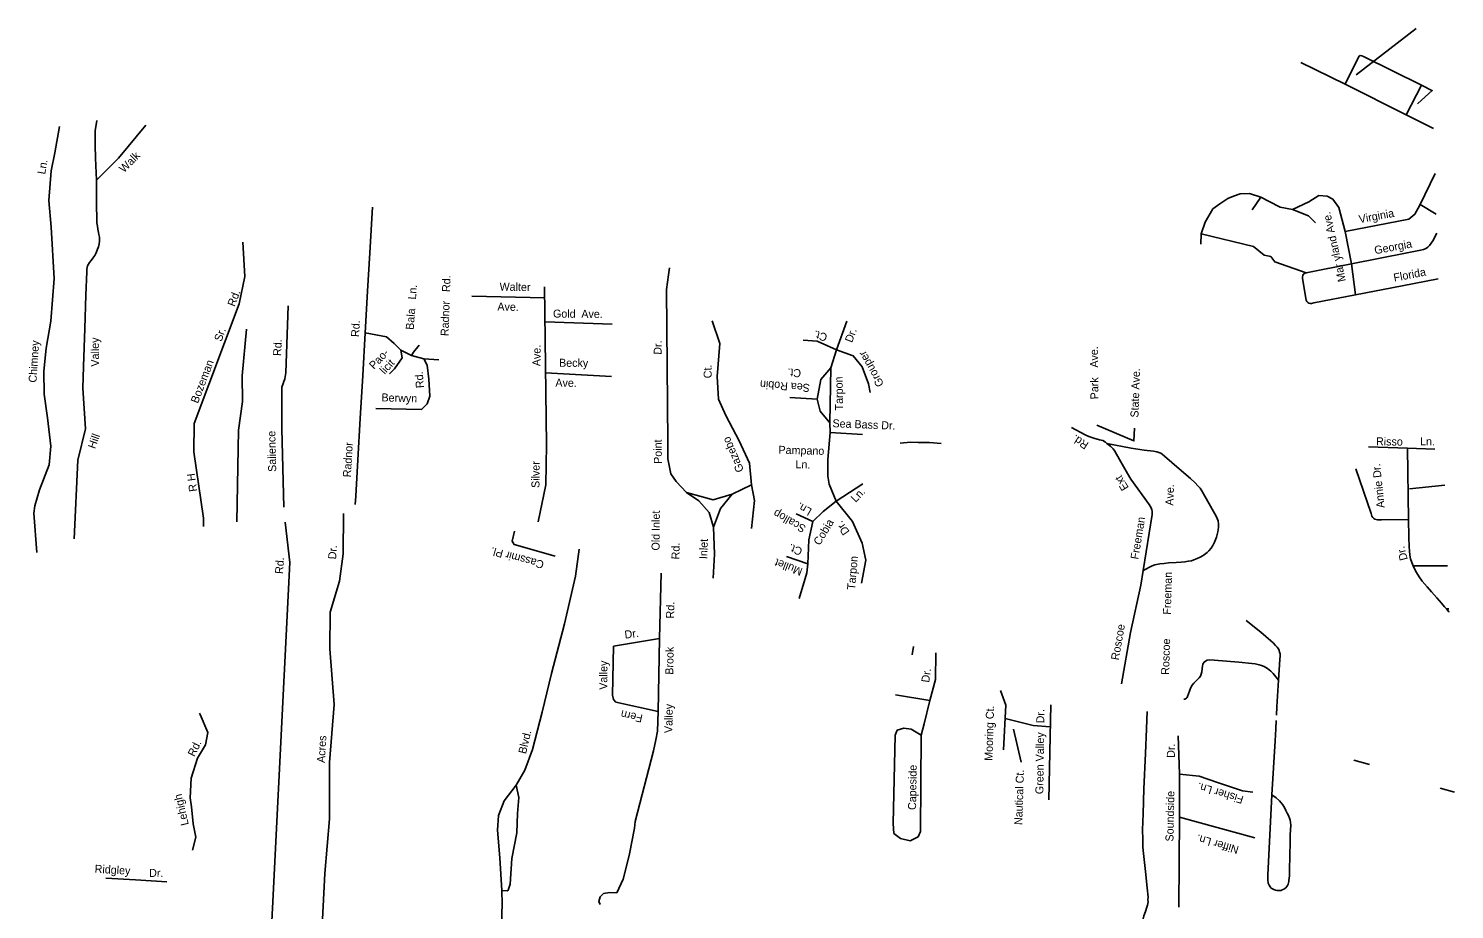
# Model space of a CAD drawing. Extents: x 2308163 to 2335412, y -96774 to 125428.
# Drawn here: x 2322147.6 to 2322238.9, y 82531.3 to 82587.7 of the extents above; entities that cross this region are included whole.
import ezdxf

# ---------------------------------------------------------------- set-up
doc = ezdxf.new("R2010")
doc.units = 0
doc.layers.add('Old_Level_10', color=7, linetype='Continuous')
doc.layers.add('Old_Level_35', color=7, linetype='Continuous')

msp = doc.modelspace()

# ---------------------------------------------------------------- linework, layer by layer
at = {"layer": 'Old_Level_10'}
for points in [[(2322236.457, 82587.723), (2322232.616, 82584.764)], [(2322237.499, 82583.786), (2322236.549, 82582.911)], [(2322218.414, 82562.132), (2322218.386, 82561.327), (2322216, 82562.337)], [(2322211.158, 82540.763), (2322210.667, 82542.876)]]:
    msp.add_lwpolyline(points, dxfattribs=at)
at = {"layer": 'Old_Level_35'}
for p, q in [((2322229.076, 82585.559), (2322231.904, 82584.161)), ((2322231.904, 82584.161), (2322235.826, 82582.192)), ((2322235.826, 82582.192), (2322236.808, 82584.088)), ((2322237.501, 82583.743), (2322236.808, 82584.088)), ((2322237.577, 82581.313), (2322235.826, 82582.192)), ((2322232.578, 82570.684), (2322232.312, 82572.661)), ((2322158.791, 82556.379), (2322158.186, 82560.62)), ((2322235.968, 82556.299), (2322235.901, 82560.854)), ((2322168.517, 82557.251), (2322168.547, 82557.791)), ((2322158.794, 82555.846), (2322158.791, 82556.379)), ((2322204.186, 82547.638), (2322204.259, 82548.168)), ((2322227.54, 82544.297), (2322227.635, 82546.009)), ((2322219.21, 82543.472), (2322219.23, 82544.005)), ((2322227.51, 82543.769), (2322227.54, 82544.297)), ((2322219.188, 82542.899), (2322219.21, 82543.472)), ((2322227.486, 82543.417), (2322227.464, 82542.889)), ((2322227.464, 82542.889), (2322227.432, 82542.121)), ((2322227.432, 82542.121), (2322227.226, 82538.671)), ((2322233.478, 82540.616), (2322232.468, 82540.875)), ((2322238.915, 82538.845), (2322238.006, 82539.101))]:
    msp.add_line(p, q, dxfattribs=at)
for points in [[(2322236.808, 82584.088), (2322233.086, 82585.929), (2322232.976, 82585.985), (2322232.884, 82586), (2322232.807, 82585.954), (2322232.774, 82585.89), (2322231.904, 82584.161)], [(2322149.281, 82579.757), (2322149.577, 82581.451)], [(2322151.947, 82578.012), (2322151.889, 82579.421), (2322151.862, 82580.249), (2322151.852, 82580.592), (2322151.867, 82581.171), (2322151.961, 82581.825)], [(2322155.112, 82581.546), (2322153.357, 82579.416), (2322151.947, 82578.012)], [(2322148.115, 82554.183), (2322147.93, 82556.697), (2322147.986, 82557.171), (2322148.299, 82558.191), (2322148.91, 82559.795), (2322149.03, 82560.979), (2322148.815, 82562.81), (2322148.59, 82564.324), (2322148.561, 82565.791), (2322148.731, 82567.252), (2322149.028, 82568.985), (2322149.242, 82571.713), (2322149.038, 82575.009), (2322148.899, 82576.718), (2322149.043, 82578.615), (2322149.281, 82579.757)], [(2322151.079, 82564.694), (2322151.112, 82566.089), (2322151.187, 82568.526), (2322151.254, 82570.663), (2322151.323, 82572.147), (2322151.325, 82572.321), (2322151.337, 82572.426), (2322151.362, 82572.539), (2322151.428, 82572.645), (2322151.497, 82572.737), (2322151.604, 82572.876), (2322151.718, 82573.03), (2322151.828, 82573.195), (2322151.917, 82573.364), (2322152.013, 82573.601), (2322152.063, 82573.757), (2322152.106, 82573.937), (2322152.128, 82574.101), (2322152.127, 82574.232), (2322152.127, 82574.365), (2322152.103, 82574.529), (2322152.079, 82574.662), (2322152.029, 82574.872), (2322152, 82575.061), (2322151.976, 82575.276), (2322151.946, 82576.667), (2322151.947, 82578.012)], [(2322236.697, 82576.415), (2322237.668, 82578.445)], [(2322232.312, 82572.661), (2322231.914, 82574.724), (2322231.503, 82576.263), (2322231.123, 82576.806), (2322230.764, 82576.985), (2322230.235, 82577.036), (2322229.591, 82576.627), (2322228.545, 82576.133), (2322227.755, 82576.293), (2322227.037, 82576.649), (2322226.516, 82576.932), (2322225.794, 82577.156), (2322225.196, 82577.143), (2322224.76, 82576.993), (2322224.39, 82576.84), (2322223.88, 82576.493), (2322223.438, 82576.176), (2322222.944, 82575.331), (2322222.686, 82574.578), (2322222.663, 82573.916)], [(2322226.516, 82576.932), (2322225.957, 82576.123)], [(2322168.547, 82557.791), (2322168.681, 82560.112), (2322168.836, 82562.767), (2322168.999, 82565.515), (2322169.158, 82568.244), (2322169.3, 82570.915), (2322169.455, 82573.365), (2322169.617, 82576.289)], [(2322228.545, 82576.133), (2322229.56, 82575.733), (2322230.009, 82575.287)], [(2322231.914, 82574.724), (2322236.002, 82575.511), (2322236.378, 82575.83), (2322236.697, 82576.415)], [(2322237.75, 82575.835), (2322236.716, 82576.455)], [(2322222.686, 82574.578), (2322226.042, 82573.766), (2322226.719, 82573.212), (2322227.148, 82573.131), (2322227.402, 82572.791), (2322229.427, 82572.078)], [(2322232.312, 82572.661), (2322235.878, 82573.373), (2322236.633, 82573.51), (2322236.838, 82573.552), (2322236.932, 82573.581), (2322237.042, 82573.627), (2322237.114, 82573.669), (2322237.201, 82573.731), (2322237.305, 82573.829), (2322237.425, 82573.975), (2322237.521, 82574.129), (2322237.788, 82574.621)], [(2322158.186, 82560.62), (2322158.201, 82562.431), (2322161.089, 82570.102), (2322161.435, 82571.854), (2322161.32, 82574.051)], [(2322191.436, 82552.543), (2322191.534, 82554.074), (2322191.458, 82555.792), (2322191.175, 82556.749), (2322190.523, 82557.494), (2322189.728, 82558.018), (2322189.074, 82558.717), (2322188.731, 82559.226), (2322188.538, 82560.18), (2322188.528, 82561.218), (2322188.46, 82571.015), (2322188.583, 82571.958), (2322188.643, 82572.408)], [(2322232.578, 82570.684), (2322229.908, 82570.156), (2322229.75, 82570.127), (2322229.68, 82570.127), (2322229.596, 82570.147), (2322229.532, 82570.18), (2322229.457, 82570.243), (2322229.408, 82570.323), (2322229.181, 82571.72), (2322229.183, 82571.828), (2322229.2, 82571.908), (2322229.233, 82571.985), (2322229.264, 82572.021), (2322229.345, 82572.062), (2322229.427, 82572.078), (2322232.312, 82572.661)], [(2322237.88, 82571.696), (2322235.563, 82571.253), (2322232.578, 82570.684)], [(2322175.988, 82570.587), (2322180.651, 82570.474)], [(2322180.232, 82556.134), (2322180.721, 82558.509), (2322180.764, 82561.08), (2322180.642, 82571.179)], [(2322163.933, 82557.08), (2322163.813, 82562.093), (2322163.814, 82564.756), (2322164.013, 82565.291), (2322164.071, 82565.673), (2322164.22, 82569.978)], [(2322180.669, 82568.937), (2322184.96, 82568.789)], [(2322193.9, 82558.506), (2322193.768, 82559.909), (2322193.094, 82561.332), (2322192.246, 82562.941), (2322191.786, 82563.995), (2322191.7, 82565.442), (2322191.863, 82567.558), (2322191.372, 82569.019)], [(2322199.32, 82557.461), (2322198.861, 82558.56), (2322198.788, 82559.059), (2322198.78, 82560.143), (2322198.929, 82561.853), (2322198.906, 82562.485), (2322198.982, 82566.003), (2322199.338, 82567.164), (2322199.989, 82568.992)], [(2322160.926, 82556.15), (2322161.032, 82562.009), (2322161.299, 82563.85), (2322161.265, 82565.499), (2322161.548, 82568.468)], [(2322169.158, 82568.244), (2322170.524, 82567.978), (2322171.006, 82567.555), (2322171.443, 82567.134), (2322171.516, 82566.635), (2322171.04, 82565.929), (2322170.714, 82565.624)], [(2322199.338, 82567.164), (2322198.092, 82567.704), (2322197.192, 82567.78)], [(2322171.443, 82567.134), (2322172.109, 82566.795), (2322172.252, 82567.015), (2322172.619, 82567.46)], [(2322199.338, 82567.164), (2322200.409, 82566.766), (2322200.972, 82566.07), (2322201.385, 82564.972), (2322201.502, 82564.427)], [(2322172.915, 82566.586), (2322173.126, 82566.173), (2322173.231, 82565.267), (2322173.283, 82564.181), (2322173.131, 82563.69), (2322172.758, 82563.342), (2322169.824, 82563.398)], [(2322172.109, 82566.795), (2322172.915, 82566.586), (2322173.861, 82566.509)], [(2322198.982, 82566.003), (2322198.324, 82565.259), (2322198.1, 82564.003), (2322198.299, 82563.228), (2322198.906, 82562.485)], [(2322180.709, 82565.686), (2322184.934, 82565.447)], [(2322151.079, 82564.694), (2322151.25, 82562.092), (2322150.744, 82560.088), (2322150.511, 82555.051)], [(2322198.1, 82564.003), (2322196.342, 82564.108)], [(2322198.929, 82561.853), (2322201.003, 82561.736)], [(2322214.38, 82562.179), (2322215.259, 82561.72), (2322215.492, 82561.606), (2322215.818, 82561.502), (2322216.172, 82561.402), (2322216.39, 82561.349), (2322216.563, 82561.252), (2322216.653, 82561.156)], [(2322206.034, 82561.168), (2322205.285, 82561.213), (2322204.573, 82561.218), (2322204.079, 82561.235), (2322203.425, 82561.179)], [(2322218.973, 82553.035), (2322219.56, 82556.602), (2322219.562, 82556.694), (2322219.549, 82556.817), (2322219.536, 82556.917), (2322219.52, 82556.981), (2322219.497, 82557.042), (2322219.357, 82557.259), (2322218.191, 82558.883), (2322217.982, 82559.233), (2322217.548, 82559.992), (2322217.276, 82560.467), (2322217.173, 82560.658), (2322217.051, 82560.817), (2322216.912, 82560.962), (2322216.653, 82561.156)], [(2322216.653, 82561.156), (2322218.209, 82560.866), (2322219.05, 82560.74), (2322219.643, 82560.663), (2322219.861, 82560.626), (2322219.984, 82560.59), (2322220.107, 82560.537), (2322220.202, 82560.476), (2322220.339, 82560.349), (2322221.288, 82559.526), (2322222.006, 82558.917), (2322222.312, 82558.642), (2322222.482, 82558.453), (2322222.619, 82558.292), (2322222.74, 82558.134), (2322222.919, 82557.784), (2322223.49, 82556.801), (2322223.653, 82556.502), (2322223.712, 82556.351), (2322223.772, 82556.202), (2322223.809, 82555.995), (2322223.807, 82555.795), (2322223.788, 82555.639), (2322223.765, 82555.498), (2322223.677, 82555.162), (2322223.551, 82554.846), (2322223.437, 82554.63), (2322223.322, 82554.46), (2322223.177, 82554.278), (2322223.083, 82554.185), (2322223.001, 82554.11), (2322222.817, 82553.981), (2322222.636, 82553.883), (2322222.436, 82553.787), (2322222.219, 82553.702), (2322222.081, 82553.652), (2322221.868, 82553.615), (2322221.646, 82553.578), (2322221.402, 82553.564), (2322221.082, 82553.545), (2322220.596, 82553.509), (2322220.329, 82553.485), (2322220.045, 82553.445), (2322219.733, 82553.389), (2322219.559, 82553.332), (2322218.973, 82553.035)], [(2322233.416, 82560.94), (2322235.901, 82560.854)], [(2322235.901, 82560.854), (2322237.657, 82560.794)], [(2322235.968, 82556.299), (2322234.246, 82556.277), (2322234.059, 82556.266), (2322233.998, 82556.269), (2322233.903, 82556.286), (2322233.815, 82556.309), (2322233.751, 82556.347), (2322233.677, 82556.421), (2322233.627, 82556.51), (2322233.586, 82556.669), (2322232.605, 82559.539)], [(2322189.728, 82558.018), (2322191.428, 82557.553), (2322192.66, 82557.917)], [(2322191.458, 82555.792), (2322191.906, 82556.995), (2322192.66, 82557.917), (2322193.9, 82558.506), (2322194.091, 82557.506), (2322193.894, 82555.708)], [(2322199.32, 82557.461), (2322201.029, 82558.576)], [(2322238.296, 82558.493), (2322236.044, 82558.263)], [(2322197.83, 82556.159), (2322198.485, 82556.813), (2322199.32, 82557.461), (2322200.359, 82556.162), (2322200.989, 82554.786), (2322201.222, 82553.695), (2322200.945, 82552.215)], [(2322162.862, 82524.179), (2322164.333, 82553.534), (2322164.021, 82556.122)], [(2322166.051, 82523.577), (2322166.57, 82533.639), (2322166.862, 82537.123), (2322166.872, 82540.731), (2322167.172, 82544.444), (2322166.894, 82548.004), (2322166.917, 82550.352), (2322167.502, 82552.336), (2322167.735, 82554.104), (2322167.766, 82556.68)], [(2322197.511, 82553.462), (2322197.564, 82554.994), (2322197.83, 82556.159), (2322196.762, 82556.647)], [(2322236.269, 82553.336), (2322236.181, 82553.543), (2322236.108, 82553.778), (2322236.066, 82553.999), (2322236.029, 82554.28), (2322236.005, 82554.546), (2322235.986, 82555.174), (2322235.968, 82556.299)], [(2322181.317, 82553.95), (2322178.69, 82554.695), (2322178.566, 82554.896), (2322178.706, 82555.555)], [(2322179.416, 82520.668), (2322178.952, 82521.469), (2322178.633, 82521.71), (2322177.923, 82525.825), (2322177.862, 82526.907), (2322177.814, 82528.348), (2322177.929, 82531.682), (2322177.893, 82532.534), (2322177.769, 82534.633), (2322177.633, 82536.405), (2322177.699, 82537.352), (2322178.058, 82538.288), (2322178.813, 82539.277), (2322179.37, 82540.24), (2322179.874, 82541.564), (2322180.481, 82543.965), (2322181.09, 82546.431), (2322181.92, 82549.609), (2322182.615, 82552.662), (2322182.851, 82554.384)], [(2322196.937, 82551.225), (2322197.445, 82552.877), (2322197.511, 82553.462), (2322196.126, 82553.916)], [(2322238.552, 82550.361), (2322238.544, 82550.375), (2322238.407, 82550.567), (2322238.286, 82550.709), (2322238.09, 82550.931), (2322237.784, 82551.268), (2322237.451, 82551.653), (2322237.176, 82551.972), (2322236.851, 82552.342), (2322236.662, 82552.623), (2322236.479, 82552.909), (2322236.36, 82553.131), (2322236.269, 82553.336)], [(2322238.459, 82553.333), (2322238.381, 82553.334), (2322236.269, 82553.336)], [(2322188.099, 82552.846), (2322188.005, 82548.666), (2322185.057, 82548.179), (2322184.998, 82545.039), (2322185.054, 82544.759), (2322185.212, 82544.59), (2322187.926, 82544.006), (2322188.005, 82548.666)], [(2322217.58, 82545.766), (2322218.158, 82549.067), (2322218.824, 82552.083), (2322218.973, 82553.035)], [(2322238.407, 82550.567), (2322238.546, 82550.576)], [(2322227.635, 82546.009), (2322227.731, 82547.336), (2322227.751, 82547.57), (2322227.747, 82547.687), (2322227.719, 82547.808), (2322227.682, 82547.915), (2322227.636, 82548.015), (2322227.561, 82548.122), (2322227.458, 82548.234), (2322227.303, 82548.395), (2322227.149, 82548.522), (2322226.506, 82549.07), (2322225.572, 82549.826)], [(2322205.699, 82547.755), (2322205.677, 82546.051), (2322205.316, 82544.71), (2322203.122, 82545.069)], [(2322221.585, 82544.785), (2322221.636, 82544.792), (2322221.692, 82544.821), (2322221.745, 82544.854), (2322221.786, 82544.901), (2322221.827, 82544.96), (2322221.877, 82545.132), (2322221.943, 82545.301), (2322222.011, 82545.486), (2322222.126, 82545.687), (2322222.222, 82545.813), (2322222.398, 82545.993), (2322222.559, 82546.163), (2322222.64, 82546.271), (2322222.694, 82546.394), (2322222.741, 82546.548), (2322222.761, 82546.735), (2322222.786, 82546.92), (2322222.801, 82547.007), (2322222.821, 82547.084), (2322222.882, 82547.164), (2322222.974, 82547.233), (2322223.071, 82547.277), (2322223.196, 82547.303), (2322223.524, 82547.279), (2322225.101, 82547.149), (2322225.942, 82547.066), (2322226.16, 82547.044), (2322226.411, 82546.994), (2322226.565, 82546.941), (2322226.737, 82546.875), (2322226.93, 82546.751), (2322227.159, 82546.572), (2322227.303, 82546.43), (2322227.635, 82546.009)], [(2322209.849, 82545.341), (2322210.189, 82544.416), (2322210.028, 82541.556)], [(2322187.926, 82544.006), (2322187.882, 82542.731), (2322187.765, 82542.179), (2322187.626, 82541.48), (2322186.439, 82536.965), (2322186.391, 82536.525), (2322186.073, 82534.884), (2322186.014, 82534.607), (2322185.673, 82533.261), (2322185.266, 82532.391), (2322184.825, 82532.407), (2322184.413, 82532.339), (2322184.193, 82532.134), (2322184.117, 82531.842), (2322184.209, 82531.643)], [(2322205.316, 82544.71), (2322204.949, 82543.211), (2322204.767, 82542.493), (2322204.711, 82536.324), (2322204.574, 82535.982), (2322204.06, 82535.716), (2322203.435, 82535.864), (2322203.005, 82536.194), (2322202.964, 82536.825), (2322203.096, 82542.488), (2322203.233, 82542.798), (2322203.648, 82542.941), (2322204.118, 82542.862), (2322204.767, 82542.493)], [(2322212.942, 82538.338), (2322213.054, 82544.421)], [(2322158.54, 82543.9), (2322158.577, 82543.819), (2322159.069, 82542.665), (2322158.927, 82541.871), (2322158.403, 82541.014), (2322158.016, 82539.733), (2322157.935, 82538.481), (2322158.029, 82537.907), (2322158.143, 82536.799), (2322158.304, 82535.957), (2322158.085, 82535.127)], [(2322210.14, 82543.542), (2322211.94, 82543.096), (2322213.028, 82543.022)], [(2322218.877, 82530.36), (2322218.914, 82530.492), (2322218.967, 82530.725), (2322219.017, 82530.928), (2322219.118, 82531.205), (2322219.204, 82531.47), (2322219.254, 82531.611), (2322219.272, 82531.719), (2322219.289, 82531.811), (2322219.276, 82531.952), (2322219.295, 82532.108), (2322219.233, 82532.72), (2322219.133, 82533.755), (2322219.005, 82534.915), (2322218.951, 82535.307), (2322218.949, 82535.822), (2322218.933, 82536.431), (2322218.972, 82537.446), (2322219.025, 82539.04), (2322219.127, 82541.303), (2322219.188, 82542.899)], [(2322221.301, 82539.994), (2322221.22, 82542.45)], [(2322221.272, 82531.475), (2322221.305, 82537.242), (2322221.301, 82539.994)], [(2322221.301, 82539.994), (2322222.557, 82539.851), (2322223.737, 82539.446), (2322225.345, 82538.927), (2322226.005, 82538.837)], [(2322178.813, 82539.277), (2322178.982, 82538.492), (2322178.915, 82537.48), (2322178.872, 82536.238), (2322178.553, 82534.58), (2322178.431, 82532.948), (2322178.319, 82532.559), (2322178.253, 82532.529), (2322177.893, 82532.534)], [(2322227.226, 82538.671), (2322226.96, 82533.52), (2322226.961, 82533.215), (2322226.98, 82533.012), (2322227.037, 82532.877), (2322227.102, 82532.782), (2322227.184, 82532.698), (2322227.251, 82532.652), (2322227.343, 82532.602), (2322227.446, 82532.566), (2322227.559, 82532.536), (2322227.656, 82532.531), (2322227.715, 82532.534), (2322227.807, 82532.55), (2322227.876, 82532.574), (2322227.979, 82532.618), (2322228.05, 82532.664), (2322228.111, 82532.711), (2322228.178, 82532.788), (2322228.226, 82532.862), (2322228.259, 82532.939), (2322228.287, 82533.039), (2322228.302, 82533.114), (2322228.317, 82533.209), (2322228.331, 82533.314), (2322228.351, 82533.501), (2322228.355, 82533.721), (2322228.359, 82533.86), (2322228.386, 82535.658), (2322228.397, 82536.112), (2322228.416, 82536.432), (2322228.427, 82536.704), (2322228.413, 82536.924), (2322228.385, 82537.037), (2322228.345, 82537.175), (2322228.283, 82537.341), (2322228.208, 82537.492), (2322228.123, 82537.666), (2322228.043, 82537.806), (2322227.913, 82538.016), (2322227.808, 82538.159), (2322227.715, 82538.271), (2322227.494, 82538.465), (2322227.226, 82538.671)], [(2322221.305, 82537.242), (2322226.137, 82535.915)], [(2322152.541, 82533.34), (2322154.441, 82533.229), (2322156.454, 82533.091)]]:
    msp.add_lwpolyline(points, dxfattribs=at)

# ---------------------------------------------------------------- texts
at = {"layer": 'Old_Level_10'}
for s, height, rotation, p in [('Walk', 0.5126, 45.38719, (2322153.705, 82578.455)), ('Ln.', 0.5126, 80.18579, (2322148.655, 82578.362)), ('Mar yland Ave.', 0.51263, 102.8292, (2322231.965, 82571.567)), ('Virginia', 0.5126, 10.49306, (2322232.837, 82575.259)), ('Georgia', 0.5126, 10.48126, (2322233.832, 82573.27)), ('Florida', 0.5126, 11.00888, (2322235.064, 82571.516)), ('Radnor   Rd.', 0.51263, 88.15233, (2322174.491, 82568.028)), ('Walter', 0.5126, 358.73813, (2322177.753, 82570.952)), ('Bozeman       Sr.        Rd.', 0.51263, 69.19482, (2322158.437, 82563.688)), ('Bala   Ln.', 0.5126, 85.75423, (2322172.257, 82568.422)), ('Ave.', 0.5126, 358.73813, (2322177.615, 82569.673)), ('Gold', 0.5126, 359.40928, (2322181.179, 82569.22)), ('Ave.', 0.5126, 359.40928, (2322182.993, 82569.204)), ('Rd.', 0.5126, 86.93568, (2322168.758, 82567.964)), ('Chimney', 0.5126, 86.24859, (2322148.099, 82565.042)), ('Valley', 0.5126, 90.4143, (2322152.109, 82566.081)), ('Rd.', 0.5126, 87.60863, (2322163.767, 82566.751)), ('Ct.', 0.5126, 163.82832, (2322198.794, 82568.164)), ('Dr.', 0.5126, 69.38486, (2322200.333, 82567.578)), ('Pao-', 0.5126, 46.90689, (2322169.721, 82565.867)), ('Ave.', 0.5126, 89.52292, (2322180.377, 82566.105)), ('Dr.', 0.5126, 89.4605, (2322188.137, 82566.84)), ('Grouper', 0.5126, 119.42301, (2322202.397, 82564.957)), ('Ave.', 0.5126, 90.57036, (2322216.094, 82566.016)), ('licit', 0.5126, 46.90689, (2322170.401, 82565.549)), ('Becky', 0.5126, 359.39522, (2322181.568, 82566.073)), ('Ct.', 0.5126, 91.0081, (2322191.347, 82565.335)), ('Ct.', 0.5126, 175.71507, (2322197.087, 82565.9)), ('State Ave.', 0.5126, 88.02472, (2322218.671, 82562.813)), ('Rd.', 0.5126, 94.31649, (2322172.917, 82564.72)), ('Ave.', 0.5126, 359.39522, (2322181.332, 82564.794)), ('       Sea Robin ', 0.51263, 175.71507, (2322198.976, 82564.859)), ('Tarpon', 0.5126, 90.96878, (2322199.761, 82563.276)), ('Park', 0.5126, 90.57036, (2322216.114, 82563.985)), ('Berwyn', 0.5126, 358.1695, (2322170.19, 82563.856)), ('Sea Bass Dr.', 0.51263, 357.76224, (2322199.073, 82562.2)), ('Hill ', 0.5126, 70.57017, (2322151.859, 82560.779)), ('Salience', 0.5126, 91.3925, (2322163.456, 82559.347)), ('Point', 0.5126, 90.4182, (2322188.153, 82559.856)), ('Gazebo', 0.5126, 113.08233, (2322193.42, 82559.441)), ('Rd.', 0.5126, 147.56716, (2322215.533, 82561.182)), ('Risso', 0.5126, 359.23122, (2322233.889, 82561.043)), ('Ln.', 0.5126, 359.78718, (2322236.713, 82561.038)), ('Radnor', 0.5126, 86.71925, (2322168.231, 82558.983)), ('Pampano ', 0.5126, 358.56772, (2322195.617, 82560.5)), ('Silver', 0.5126, 89.52253, (2322180.312, 82558.31)), ('Ln.', 0.5126, 358.56772, (2322196.704, 82559.575)), ('Annie Dr.', 0.5126, 96.08257, (2322234.449, 82557.051)), ('R H', 0.5126, 97.68715, (2322158.391, 82558.105)), ('Ext', 0.5126, 120.87874, (2322218.074, 82558.329)), ('Ln.', 0.5126, 45.7345, (2322200.558, 82557.351)), ('Ave.', 0.5126, 88.36506, (2322220.911, 82557.174)), ('Old Inlet', 0.5126, 89.48366, (2322188.004, 82554.304)), ('Scallop ', 0.5126, 150.38519, (2322197.428, 82555.855)), ('Ln.', 0.5126, 150.38519, (2322197.806, 82556.95)), ('Cobia', 0.5126, 58.95245, (2322198.265, 82554.594)), ('Dr.', 0.5126, 125.53608, (2322200.201, 82555.516)), ('Freeman', 0.5126, 80.65612, (2322218.664, 82553.711)), ('Inlet', 0.5126, 88.02472, (2322191.056, 82553.75)), ('Dr.', 0.5126, 85.98926, (2322167.285, 82553.73)), ('Cassmir Pl.', 0.51263, 164.86716, (2322180.643, 82553.619)), ('Rd.', 0.5126, 89.48366, (2322189.281, 82553.736)), ('Ct.', 0.5126, 159.12015, (2322197.201, 82554.443)), ('Dr.', 0.5126, 104.75812, (2322235.927, 82553.741)), ('Rd.', 0.5126, 85.89384, (2322163.885, 82552.792)), ('Mullet', 0.5126, 159.12015, (2322197.211, 82553.151)), ('Tarpon', 0.5126, 84.96368, (2322200.519, 82551.773)), ('Freeman', 0.5126, 88.36506, (2322220.75, 82550.192)), ('Rd.', 0.5126, 89.1148, (2322188.938, 82549.954)), ('Roscoe', 0.5126, 79.98655, (2322217.411, 82547.258)), ('Dr.', 0.5126, 7.31703, (2322185.795, 82548.662)), ('Roscoe ', 0.5126, 88.36506, (2322220.639, 82546.342)), ('Brook', 0.5126, 89.11451, (2322188.882, 82546.353)), ('Valley', 0.5126, 89.34598, (2322184.65, 82545.388)), ('Dr.', 0.5126, 82.12929, (2322205.271, 82545.83)), ('Fern', 0.5126, 167.80014, (2322186.961, 82543.788)), ('Valley', 0.5126, 89.11338, (2322188.824, 82542.616)), ('Mooring Ct.', 0.51263, 88.26116, (2322209.324, 82540.836)), ('Green Valley   Dr.', 0.51263, 89.29644, (2322212.584, 82538.706)), ('Acres', 0.5126, 86.63312, (2322166.566, 82540.699)), ('Blvd.', 0.5126, 76.55392, (2322179.447, 82541.252)), ('Rd.', 0.5126, 63.66991, (2322158.215, 82541.066)), ('Dr.', 0.5126, 89.64489, (2322221.005, 82541.033)), ('Capeside', 0.5126, 89.10122, (2322204.429, 82537.692)), ('Nautical Ct.', 0.51263, 88.02472, (2322211.227, 82536.726)), ('Fisher Ln.', 0.5126, 162.94304, (2322225.448, 82538.568)), ('Lehigh', 0.5126, 103.2557, (2322157.86, 82536.762)), ('Soundside ', 0.5126, 88.85475, (2322220.914, 82535.674)), ('Niffer Ln.', 0.5126, 163.63217, (2322225.143, 82535.358)), ('Ridgley', 0.5126, 356.74322, (2322151.817, 82533.68)), ('Dr.', 0.5126, 359.02815, (2322155.31, 82533.416))]:
    msp.add_text(s, height=height, rotation=rotation, dxfattribs=at).set_placement(p)

doc.saveas('drawing.dxf')
